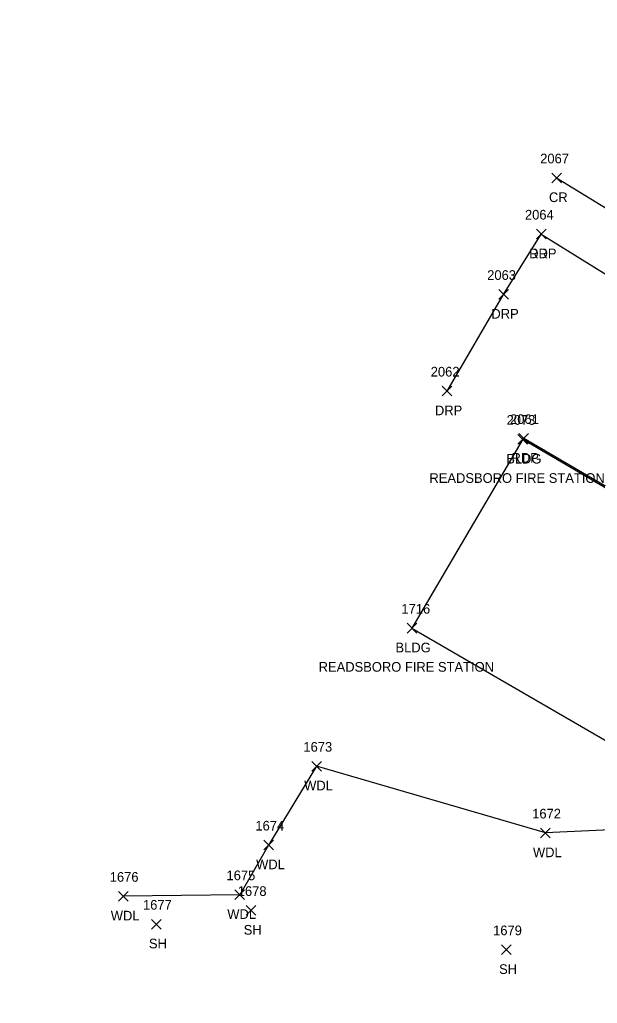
# Model space of a CAD drawing. Extents: x 462930 to 463548, y 29607 to 30453.
# Drawn here: x 463314.5 to 463350.9, y 30175.8 to 30237.8 of the extents above; entities that cross this region are included whole.
import ezdxf

# ---------------------------------------------------------------- set-up
doc = ezdxf.new("R2010")
doc.units = 0
for name, color, linetype in [('L_A', 7, 'Continuous'), ('L_C', 7, 'Continuous'), ('L_I', 7, 'Continuous'), ('L_TIC', 7, 'Continuous'), ('LAWA', 7, 'Continuous'), ('LBC', 7, 'Continuous'), ('P_A', 7, 'Continuous'), ('P_I', 7, 'Continuous'), ('P_TIC', 7, 'Continuous'), ('PET', 7, 'Continuous'), ('PRC', 7, 'Continuous'), ('R_A', 7, 'Continuous'), ('R_I', 7, 'Continuous'), ('R_TIC', 7, 'Continuous'), ('RDP', 7, 'Continuous')]:
    doc.layers.add(name, color=color, linetype=linetype)

msp = doc.modelspace()

# ---------------------------------------------------------------- linework, layer by layer
at = {"layer": 'L_TIC'}
for points in [[(463345.877, 30211.064), (463346.487, 30211.674)], [(463346.487, 30211.064), (463345.877, 30211.674)], [(463338.896, 30199.171), (463339.506, 30199.781)], [(463339.506, 30199.171), (463338.896, 30199.781)], [(463332.889, 30190.476), (463333.499, 30191.086)], [(463333.499, 30190.476), (463332.889, 30191.086)], [(463347.306, 30186.27), (463347.916, 30186.88)], [(463347.916, 30186.27), (463347.306, 30186.88)], [(463329.862, 30185.512), (463330.472, 30186.122)], [(463330.472, 30185.512), (463329.862, 30186.122)], [(463320.702, 30182.284), (463321.312, 30182.894)], [(463321.312, 30182.284), (463320.702, 30182.894)], [(463328.043, 30182.384), (463328.653, 30182.994)], [(463328.653, 30182.384), (463328.043, 30182.994)], [(463328.753, 30181.392), (463329.363, 30182.002)], [(463329.363, 30181.392), (463328.753, 30182.002)], [(463322.78, 30180.527), (463323.39, 30181.137)], [(463323.39, 30180.527), (463322.78, 30181.137)], [(463344.847, 30178.918), (463345.457, 30179.528)], [(463345.457, 30178.918), (463344.847, 30179.528)]]:
    msp.add_lwpolyline(points, dxfattribs=at)
at = {"layer": 'LAWA'}
msp.add_lwpolyline([(463334.191, 30153.632), (463326.241, 30157.391), (463319.877, 30160.227), (463314.478, 30162.732), (463317.175, 30171.812), (463324.684, 30170.939), (463329.084, 30171.282), (463333.083, 30171.461), (463343.25, 30171.173), (463352.596, 30169.581), (463356.899, 30175.447), (463361.663, 30184.45), (463356.272, 30186.994), (463347.611, 30186.575), (463333.194, 30190.781), (463330.167, 30185.817), (463328.348, 30182.689), (463321.007, 30182.589)], dxfattribs=at)
at = {"layer": 'LBC'}
for points in [[(463346.182, 30211.369), (463339.201, 30199.476)], [(463346.182, 30211.369), (463363.604, 30201.169)], [(463339.201, 30199.476), (463356.632, 30189.385)]]:
    msp.add_lwpolyline(points, dxfattribs=at)
at = {"layer": 'P_TIC'}
for points in [[(463348.007, 30227.531), (463348.617, 30228.141)], [(463348.617, 30227.531), (463348.007, 30228.141)], [(463347.047, 30223.992), (463347.657, 30224.602)], [(463347.657, 30223.992), (463347.047, 30224.602)], [(463345.936, 30211.116), (463346.546, 30211.726)], [(463346.546, 30211.116), (463345.936, 30211.726)]]:
    msp.add_lwpolyline(points, dxfattribs=at)
at = {"layer": 'PET'}
for points in [[(463391.243, 30228.803), (463383.284, 30219.654), (463378.918, 30214.508), (463373.68, 30208.043), (463363.064, 30214.586), (463356.837, 30205.224), (463346.241, 30211.421)], [(463347.352, 30224.297), (463358.252, 30217.533), (463362.923, 30214.653)]]:
    msp.add_lwpolyline(points, dxfattribs=at)
at = {"layer": 'PRC'}
msp.add_lwpolyline([(463348.312, 30227.836), (463361.835, 30219.563), (463370.226, 30217.343), (463379.946, 30221.462), (463388.333, 30230.936), (463392.855, 30237.8)], dxfattribs=at)
at = {"layer": 'R_TIC'}
for points in [[(463347.047, 30223.992), (463347.657, 30224.602)], [(463347.657, 30223.992), (463347.047, 30224.602)], [(463344.667, 30220.191), (463345.277, 30220.801)], [(463345.277, 30220.191), (463344.667, 30220.801)], [(463341.11, 30214.105), (463341.72, 30214.715)], [(463341.72, 30214.105), (463341.11, 30214.715)]]:
    msp.add_lwpolyline(points, dxfattribs=at)
at = {"layer": 'RDP'}
msp.add_lwpolyline([(463341.415, 30214.41), (463344.972, 30220.496), (463347.352, 30224.297)], dxfattribs=at)

# ---------------------------------------------------------------- texts
at = {"layer": 'L_A'}
for s, p in [('BLDG', (463345.143, 30209.845)), ('BLDG', (463338.162, 30197.952)), ('WDL', (463332.407, 30189.257)), ('WDL', (463346.824, 30185.051)), ('WDL', (463329.38, 30184.293)), ('WDL', (463320.22, 30181.065)), ('WDL', (463327.561, 30181.165)), ('SH', (463328.597, 30180.173)), ('SH', (463322.624, 30179.308)), ('SH', (463344.691, 30177.699))]:
    msp.add_text(s, height=0.6096, dxfattribs=at).set_placement(p)
at = {"layer": 'L_C'}
for p in [(463340.3, 30208.626), (463333.319, 30196.733)]:
    msp.add_text('READSBORO FIRE STATION', height=0.6096, dxfattribs=at).set_placement(p)
at = {"layer": 'L_I'}
for s, p in [('2073', (463345.164, 30212.283)), ('1716', (463338.536, 30200.39)), ('1673', (463332.359, 30191.695)), ('1672', (463346.776, 30187.489)), ('1674', (463329.332, 30186.731)), ('1676', (463320.155, 30183.503)), ('1675', (463327.513, 30183.603)), ('1678', (463328.223, 30182.611)), ('1677', (463322.25, 30181.746)), ('1679', (463344.314, 30180.137))]:
    msp.add_text(s, height=0.6096, dxfattribs=at).set_placement(p)
at = {"layer": 'P_A'}
for s, p in [('CR', (463347.834, 30226.312)), ('RDP', (463346.586, 30222.773)), ('RDP', (463345.475, 30209.897))]:
    msp.add_text(s, height=0.6096, dxfattribs=at).set_placement(p)
at = {"layer": 'P_I'}
for s, p in [('2067', (463347.28, 30228.75)), ('2064', (463346.32, 30225.211)), ('2061', (463345.382, 30212.335))]:
    msp.add_text(s, height=0.6096, dxfattribs=at).set_placement(p)
at = {"layer": 'R_A'}
for p in [(463346.586, 30222.773), (463344.206, 30218.972), (463340.649, 30212.886)]:
    msp.add_text('DRP', height=0.6096, dxfattribs=at).set_placement(p)
at = {"layer": 'R_I'}
for s, p in [('2064', (463346.32, 30225.211)), ('2063', (463343.94, 30221.41)), ('2062', (463340.383, 30215.324))]:
    msp.add_text(s, height=0.6096, dxfattribs=at).set_placement(p)

doc.saveas('drawing.dxf')
